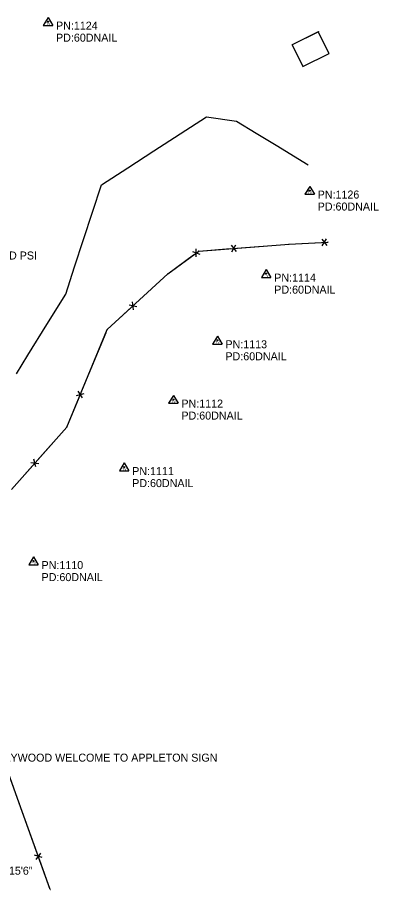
# Model space of a CAD drawing. Extents: x 1050807 to 1053552, y 395828 to 398415.
# Drawn here: x 1052315 to 1052541, y 397208 to 397753 of the extents above; entities that cross this region are included whole.
import ezdxf

# ---------------------------------------------------------------- set-up
doc = ezdxf.new("R2010")
doc.units = 0
for name, color, linetype in [('S_BUILDING', 7, 'Continuous'), ('S_DITCHLINE', 7, 'Continuous'), ('S_FENCE', 7, 'Continuous'), ('S_MISC_STRUCTURES_ANNOT', 7, 'Continuous'), ('S_MSC_PT_SYM', 7, 'Continuous'), ('S_SECONDARY_CTL', 7, 'Continuous'), ('S_SECONDARY_CTL_ANNOT', 7, 'Continuous'), ('S_SIGN_ANNOT', 7, 'Continuous'), ('S_STR_PT_SYM', 7, 'Continuous'), ('S_TANK_ANNOT', 7, 'Continuous')]:
    doc.layers.add(name, color=color, linetype=linetype)

msp = doc.modelspace()

# ---------------------------------------------------------------- linework, layer by layer
at = {"layer": 'S_BUILDING'}
for p, q in [((1052503.27, 397744.02), (1052486.82, 397735.82)), ((1052503.2, 397743.99), (1052486.82, 397735.82)), ((1052509.98, 397730.38), (1052503.2, 397743.99)), ((1052486.82, 397735.82), (1052493.6, 397722.22)), ((1052493.6, 397722.22), (1052509.98, 397730.38))]:
    msp.add_line(p, q, dxfattribs=at)
at = {"layer": 'S_DITCHLINE'}
msp.add_lwpolyline([(1052314.61, 397530.28), (1052321.73, 397542.03), (1052333.57, 397561.09), (1052345.41, 397580.16), (1052350.99, 397597.23), (1052356.57, 397614.3), (1052362.15, 397631.37), (1052367.73, 397648.44), (1052384.12, 397659.03), (1052400.52, 397669.61), (1052416.91, 397680.19), (1052433.3, 397690.78), (1052452.07, 397688.07), (1052464.51, 397680.62), (1052476.95, 397673.17), (1052496.88, 397660.87)], dxfattribs=at)
at = {"layer": 'S_FENCE'}
for p, q in [((1052505.44, 397614.45), (1052508.5, 397610.5)), ((1052505.44, 397614.45), (1052508.5, 397610.5)), ((1052505.63, 397610.36), (1052508.3, 397614.59)), ((1052505.63, 397610.36), (1052508.3, 397614.59)), ((1052427, 397603.43), (1052426.88, 397608.43)), ((1052427, 397603.43), (1052426.88, 397608.43)), ((1052428.48, 397607.07), (1052484.99, 397611.41)), ((1052448.83, 397610.69), (1052452, 397606.82)), ((1052448.83, 397610.69), (1052452, 397606.82)), ((1052449.14, 397606.6), (1052451.69, 397610.91)), ((1052449.14, 397606.6), (1052451.69, 397610.91)), ((1052484.99, 397611.41), (1052509.33, 397612.59)), ((1052409.24, 397592.87), (1052428.48, 397607.07)), ((1052424.57, 397606.73), (1052429.31, 397605.14)), ((1052424.57, 397606.73), (1052429.31, 397605.14)), ((1052371.28, 397557.97), (1052409.24, 397592.87)), ((1052387.8, 397570.38), (1052387.14, 397575.34)), ((1052387.8, 397570.38), (1052387.14, 397575.34)), ((1052385.03, 397573.4), (1052389.91, 397572.32)), ((1052385.03, 397573.4), (1052389.91, 397572.32)), ((1052346.09, 397497.15), (1052371.28, 397557.97)), ((1052352.07, 397516.93), (1052356.95, 397518.02)), ((1052352.07, 397516.93), (1052356.95, 397518.02)), ((1052355.85, 397515.37), (1052353.17, 397519.58)), ((1052355.85, 397515.37), (1052353.17, 397519.58)), ((1052311.53, 397458.24), (1052346.09, 397497.15)), ((1052326.72, 397472.25), (1052325.56, 397477.12)), ((1052326.72, 397472.25), (1052325.56, 397477.12)), ((1052323.66, 397474.98), (1052328.63, 397474.4)), ((1052323.66, 397474.98), (1052328.63, 397474.4)), ((1052316.4, 397262.22), (1052292.16, 397329.1)), ((1052335.78, 397208.41), (1052316.4, 397262.22)), ((1052330.74, 397228.45), (1052325.91, 397229.76)), ((1052330.74, 397228.45), (1052325.91, 397229.76)), ((1052326.88, 397227.06), (1052329.76, 397231.15)), ((1052326.88, 397227.06), (1052329.76, 397231.15))]:
    msp.add_line(p, q, dxfattribs=at)
for points in [[(1052428.48, 397607.07), (1052448.42, 397608.6)], [(1052428.48, 397607.07), (1052448.42, 397608.6)], [(1052452.41, 397608.91), (1052484.99, 397611.41)], [(1052452.41, 397608.91), (1052484.99, 397611.41)], [(1052484.99, 397611.41), (1052504.97, 397612.38)], [(1052484.99, 397611.41), (1052504.97, 397612.38)], [(1052508.97, 397612.57), (1052509.33, 397612.59)], [(1052508.97, 397612.57), (1052509.33, 397612.59)], [(1052409.24, 397592.87), (1052425.33, 397604.74)], [(1052409.24, 397592.87), (1052425.33, 397604.74)], [(1052388.95, 397574.21), (1052409.24, 397592.87)], [(1052388.95, 397574.21), (1052409.24, 397592.87)], [(1052371.28, 397557.97), (1052386, 397571.51)], [(1052371.28, 397557.97), (1052386, 397571.51)], [(1052355.28, 397519.32), (1052370.58, 397556.28)], [(1052355.28, 397519.32), (1052370.58, 397556.28)], [(1052346.09, 397497.15), (1052353.75, 397515.63)], [(1052346.09, 397497.15), (1052353.75, 397515.63)], [(1052327.47, 397476.18), (1052346.09, 397497.15)], [(1052327.47, 397476.18), (1052346.09, 397497.15)], [(1052311.53, 397458.24), (1052324.82, 397473.19)], [(1052311.53, 397458.24), (1052324.82, 397473.19)], [(1052316.4, 397262.22), (1052309.58, 397281.02)], [(1052316.4, 397262.22), (1052309.58, 397281.02)], [(1052327.65, 397230.99), (1052316.4, 397262.22)], [(1052327.65, 397230.99), (1052316.4, 397262.22)], [(1052335.78, 397208.41), (1052329, 397227.22)], [(1052335.78, 397208.41), (1052329, 397227.22)]]:
    msp.add_lwpolyline(points, dxfattribs=at)
at = {"layer": 'S_MSC_PT_SYM'}
for points in [[(1052509.33, 397612.59), (1052509.33, 397612.64), (1052509.33, 397612.59), (1052509.28, 397612.59), (1052509.33, 397612.59), (1052509.33, 397612.54), (1052509.33, 397612.59), (1052509.38, 397612.59)], [(1052484.99, 397611.41), (1052484.99, 397611.46), (1052484.99, 397611.41), (1052484.94, 397611.41), (1052484.99, 397611.41), (1052484.99, 397611.36), (1052484.99, 397611.41), (1052485.04, 397611.41)], [(1052428.48, 397607.07), (1052428.48, 397607.12), (1052428.48, 397607.07), (1052428.43, 397607.07), (1052428.48, 397607.07), (1052428.48, 397607.02), (1052428.48, 397607.07), (1052428.53, 397607.07)], [(1052409.24, 397592.87), (1052409.24, 397592.92), (1052409.24, 397592.87), (1052409.19, 397592.87), (1052409.24, 397592.87), (1052409.24, 397592.82), (1052409.24, 397592.87), (1052409.29, 397592.87)], [(1052371.28, 397557.97), (1052371.28, 397558.02), (1052371.28, 397557.97), (1052371.23, 397557.97), (1052371.28, 397557.97), (1052371.28, 397557.92), (1052371.28, 397557.97), (1052371.33, 397557.97)], [(1052346.09, 397497.15), (1052346.09, 397497.2), (1052346.09, 397497.15), (1052346.04, 397497.15), (1052346.09, 397497.15), (1052346.09, 397497.1), (1052346.09, 397497.15), (1052346.14, 397497.15)], [(1052316.4, 397262.22), (1052316.4, 397262.27), (1052316.4, 397262.22), (1052316.35, 397262.22), (1052316.4, 397262.22), (1052316.4, 397262.17), (1052316.4, 397262.22), (1052316.45, 397262.22)], [(1052335.78, 397208.41), (1052335.78, 397208.46), (1052335.78, 397208.41), (1052335.73, 397208.41), (1052335.78, 397208.41), (1052335.78, 397208.36), (1052335.78, 397208.41), (1052335.83, 397208.41)]]:
    msp.add_lwpolyline(points, dxfattribs=at)
at = {"layer": 'S_SECONDARY_CTL'}
for p, q in [((1052334.35, 397752.9), (1052331.34, 397747.95)), ((1052334.35, 397752.9), (1052337.3, 397747.95)), ((1052331.34, 397747.95), (1052337.3, 397747.95)), ((1052497.84, 397647.43), (1052494.83, 397642.48)), ((1052497.84, 397647.43), (1052500.78, 397642.48)), ((1052494.83, 397642.48), (1052500.78, 397642.48)), ((1052470.71, 397595.56), (1052467.7, 397590.61)), ((1052470.71, 397595.56), (1052473.66, 397590.61)), ((1052467.7, 397590.61), (1052473.66, 397590.61)), ((1052440.19, 397553.94), (1052437.18, 397548.99)), ((1052440.19, 397553.94), (1052443.14, 397548.99)), ((1052437.18, 397548.99), (1052443.14, 397548.99)), ((1052412.69, 397516.91), (1052409.68, 397511.96)), ((1052412.69, 397516.91), (1052415.64, 397511.96)), ((1052409.68, 397511.96), (1052415.64, 397511.96)), ((1052381.94, 397474.75), (1052378.93, 397469.79)), ((1052381.94, 397474.75), (1052384.89, 397469.79)), ((1052378.93, 397469.79), (1052384.89, 397469.79)), ((1052325.32, 397416.06), (1052322.31, 397411.11)), ((1052325.32, 397416.06), (1052328.27, 397411.11)), ((1052322.31, 397411.11), (1052328.27, 397411.11))]:
    msp.add_line(p, q, dxfattribs=at)
for centre, radius in [((1052334.35, 397750.29), 0.311), ((1052334.35, 397750.29), 0.183), ((1052334.35, 397750.29), 0.103), ((1052497.84, 397644.82), 0.311), ((1052497.84, 397644.82), 0.183), ((1052497.84, 397644.82), 0.103), ((1052470.71, 397592.95), 0.311), ((1052470.71, 397592.95), 0.183), ((1052470.71, 397592.95), 0.103), ((1052440.19, 397551.33), 0.311), ((1052440.19, 397551.33), 0.183), ((1052440.19, 397551.33), 0.103), ((1052412.69, 397514.3), 0.311), ((1052412.69, 397514.3), 0.183), ((1052412.69, 397514.3), 0.103), ((1052381.94, 397472.14), 0.311), ((1052381.94, 397472.14), 0.183), ((1052381.94, 397472.14), 0.103), ((1052325.32, 397413.45), 0.311), ((1052325.32, 397413.45), 0.183), ((1052325.32, 397413.45), 0.103)]:
    msp.add_circle(centre, radius, dxfattribs=at)
at = {"layer": 'S_STR_PT_SYM'}
for points in [[(1052503.2, 397743.99), (1052503.2, 397744.04), (1052503.2, 397743.99), (1052503.15, 397743.99), (1052503.2, 397743.99), (1052503.2, 397743.94), (1052503.2, 397743.99), (1052503.25, 397743.99)], [(1052503.27, 397744.02), (1052503.27, 397744.07), (1052503.27, 397744.02), (1052503.22, 397744.02), (1052503.27, 397744.02), (1052503.27, 397743.97), (1052503.27, 397744.02), (1052503.32, 397744.02)], [(1052486.82, 397735.82), (1052486.82, 397735.87), (1052486.82, 397735.82), (1052486.77, 397735.82), (1052486.82, 397735.82), (1052486.82, 397735.77), (1052486.82, 397735.82), (1052486.87, 397735.82)], [(1052486.82, 397735.82), (1052486.82, 397735.87), (1052486.82, 397735.82), (1052486.77, 397735.82), (1052486.82, 397735.82), (1052486.82, 397735.77), (1052486.82, 397735.82), (1052486.87, 397735.82)], [(1052509.98, 397730.38), (1052509.98, 397730.43), (1052509.98, 397730.38), (1052509.93, 397730.38), (1052509.98, 397730.38), (1052509.98, 397730.33), (1052509.98, 397730.38), (1052510.03, 397730.38)], [(1052493.6, 397722.22), (1052493.6, 397722.27), (1052493.6, 397722.22), (1052493.55, 397722.22), (1052493.6, 397722.22), (1052493.6, 397722.17), (1052493.6, 397722.22), (1052493.65, 397722.22)]]:
    msp.add_lwpolyline(points, dxfattribs=at)

# ---------------------------------------------------------------- texts
at = {"layer": 'S_MISC_STRUCTURES_ANNOT'}
msp.add_text('CATTLE GUARD 8\'X15\'6"', height=5, dxfattribs=at).set_placement((1052246.95, 397217.65))
at = {"layer": 'S_SECONDARY_CTL'}
for p in [(1052333.14, 397748.28), (1052496.63, 397642.81), (1052469.5, 397590.94), (1052438.99, 397549.32), (1052411.48, 397512.29), (1052380.73, 397470.12), (1052324.12, 397411.44)]:
    msp.add_text('TV', height=1.5, dxfattribs=at).set_placement(p)
at = {"layer": 'S_SECONDARY_CTL_ANNOT'}
for s, p in [('PN:1124', (1052339.35, 397745.29)), ('PD:60DNAIL', (1052339.35, 397737.79)), ('PN:1126', (1052502.84, 397639.82)), ('PD:60DNAIL', (1052502.84, 397632.32)), ('PN:1114', (1052475.71, 397587.95)), ('PD:60DNAIL', (1052475.71, 397580.45)), ('PN:1113', (1052445.19, 397546.33)), ('PD:60DNAIL', (1052445.19, 397538.83)), ('PN:1112', (1052417.69, 397509.3)), ('PD:60DNAIL', (1052417.69, 397501.8)), ('PN:1111', (1052386.94, 397467.14)), ('PD:60DNAIL', (1052386.94, 397459.64)), ('PN:1110', (1052330.32, 397408.45)), ('PD:60DNAIL', (1052330.32, 397400.95))]:
    msp.add_text(s, height=5, dxfattribs=at).set_placement(p)
at = {"layer": 'S_SIGN_ANNOT'}
msp.add_text('PLYWOOD WELCOME TO APPLETON SIGN', height=5, dxfattribs=at).set_placement((1052302.74, 397288.22))
at = {"layer": 'S_TANK_ANNOT'}
msp.add_text('PROPANE TANK 200 POUND PSI', height=5, dxfattribs=at).set_placement((1052223.41, 397601.76))

doc.saveas('drawing.dxf')
